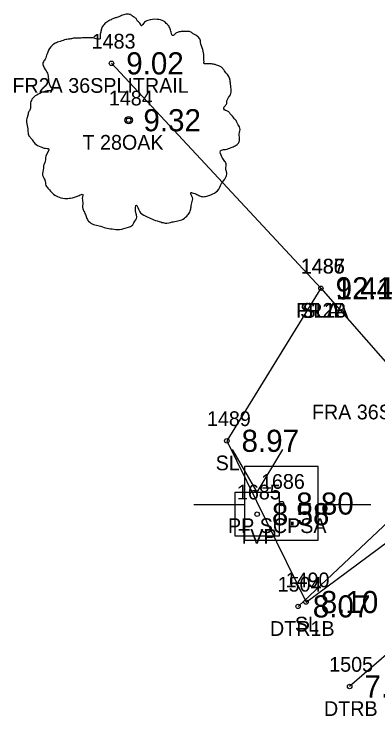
# Model space of a CAD drawing. Extents: x 2608598 to 2610682, y 641451 to 643526.
# Drawn here: x 2608857.57 to 2608882.27, y 643010.54 to 643058.15 of the extents above; entities that cross this region are included whole.
import ezdxf

# ---------------------------------------------------------------- set-up
doc = ezdxf.new("R2010")
doc.units = 0
for name, color, linetype in [('RD_EX_Fence_Other', 7, 'Continuous'), ('RD_EX_Fence_Other_txCode', 7, 'Continuous'), ('RD_EX_H2O', 7, 'Continuous'), ('RD_EX_H2O_txCode', 7, 'Continuous'), ('RD_EX_TX_Fence_Other_ELEV', 7, 'Continuous'), ('RD_EX_TX_H2O_ELEV', 7, 'Continuous'), ('RD_EX_TX_UT_ELEV', 7, 'Continuous'), ('RD_EX_TX_VEG_ELEV', 7, 'Continuous'), ('RD_EX_UT', 7, 'Continuous'), ('RD_EX_UT_txCode', 7, 'Continuous'), ('RD_EX_VEG', 7, 'Continuous'), ('RD_EX_VEG_txCode', 7, 'Continuous'), ('RD_HC_Survey_ELEV', 7, 'Continuous'), ('RD_SMD_Locator', 7, 'Continuous')]:
    doc.layers.add(name, color=color, linetype=linetype)

msp = doc.modelspace()

# ---------------------------------------------------------------- linework, layer by layer
at = {"layer": 'RD_EX_Fence_Other'}
msp.add_line((2608864.186, 643054.805), (2608878.396, 643039.549), dxfattribs=at)
at = {"layer": 'RD_EX_H2O'}
for points in [[(2608899.32, 643029.853), (2608900.685, 643033.3), (2608899.484, 643036.514), (2608896.493, 643036.436), (2608876.847, 643017.975)], [(2608899.32, 643029.853), (2608893.85, 643024.202), (2608880.346, 643012.543)]]:
    msp.add_lwpolyline(points, dxfattribs=at)
at = {"layer": 'RD_EX_UT'}
for p, q in [((2608874.068, 643025.727), (2608872.402, 643028.612)), ((2608874.068, 643025.727), (2608875.809, 643028.612)), ((2608878.212, 643027.457), (2608873.212, 643027.457)), ((2608873.212, 643027.457), (2608873.212, 643022.457)), ((2608878.212, 643022.457), (2608878.212, 643027.457)), ((2608869.781, 643024.895), (2608873.25, 643024.895)), ((2608878.141, 643024.895), (2608881.781, 643024.895)), ((2608873.212, 643022.457), (2608878.212, 643022.457))]:
    msp.add_line(p, q, dxfattribs=at)
msp.add_lwpolyline([(2608872.568, 643022.727), (2608872.568, 643025.727), (2608875.568, 643025.727), (2608875.568, 643022.727)], close=True, dxfattribs=at)
at = {"layer": 'RD_EX_VEG'}
msp.add_line((2608878.396, 643039.549), (2608889.322, 643027.092), dxfattribs=at)
msp.add_lwpolyline([(2608878.396, 643039.549), (2608872.01, 643029.204), (2608877.387, 643018.269), (2608889.322, 643027.092)], dxfattribs=at)
for centre, radius in [((2608865.351, 643050.947), 0.25), ((2608865.339, 643050.928), 0.0001)]:
    msp.add_circle(centre, radius, dxfattribs=at)
for points in [[(2608865.483, 643058.114), (2608865.183, 643058.139), (2608864.859, 643058.039), (2608864.609, 643057.939), (2608864.384, 643057.864), (2608864.159, 643057.764), (2608863.859, 643057.589), (2608863.634, 643057.389), (2608863.509, 643057.139), (2608863.459, 643056.914), (2608863.409, 643056.639), (2608863.409, 643056.464), (2608863.284, 643056.439), (2608863.134, 643056.464), (2608862.884, 643056.539), (2608862.634, 643056.539), (2608862.385, 643056.539), (2608862.035, 643056.514), (2608861.685, 643056.514), (2608861.41, 643056.464), (2608861.085, 643056.415), (2608860.71, 643056.29), (2608860.36, 643056.165), (2608860.061, 643055.915), (2608859.811, 643055.44), (2608859.686, 643055.09), (2608859.536, 643054.84), (2608859.686, 643054.39), (2608859.861, 643054.041), (2608859.886, 643053.841), (2608859.961, 643053.416), (2608860.061, 643053.191), (2608860.186, 643052.991), (2608860.111, 643052.966), (2608859.736, 643052.916), (2608859.436, 643052.816), (2608859.011, 643052.591), (2608858.786, 643052.366), (2608858.686, 643052.041), (2608858.661, 643051.692), (2608858.561, 643051.492), (2608858.486, 643051.217), (2608858.461, 643051.142), (2608858.411, 643050.817), (2608858.511, 643050.367), (2608858.536, 643050.017), (2608858.661, 643049.792), (2608858.811, 643049.618), (2608858.986, 643049.368), (2608859.386, 643049.143), (2608859.711, 643049.043), (2608859.911, 643049.018), (2608859.736, 643048.518), (2608859.686, 643048.168), (2608859.561, 643047.768), (2608859.561, 643047.693), (2608859.511, 643047.219), (2608859.661, 643046.894), (2608859.736, 643046.519), (2608859.911, 643046.294), (2608860.186, 643045.994), (2608860.51, 643045.769), (2608861.01, 643045.644), (2608861.41, 643045.669), (2608861.985, 643045.844), (2608862.235, 643045.919), (2608862.21, 643045.744), (2608862.235, 643045.369), (2608862.235, 643044.945), (2608862.385, 643044.62), (2608862.485, 643044.345), (2608862.634, 643044.095), (2608862.959, 643043.87), (2608863.359, 643043.795), (2608863.784, 643043.645), (2608864.234, 643043.57), (2608864.734, 643043.545), (2608865.333, 643043.695), (2608865.608, 643043.82), (2608865.708, 643043.995), (2608865.908, 643044.37), (2608865.858, 643044.595), (2608865.883, 643045.194), (2608865.983, 643045.019), (2608866.158, 643044.67), (2608866.658, 643044.37), (2608867.058, 643044.195), (2608867.532, 643044.045), (2608867.832, 643043.97), (2608868.307, 643044.045), (2608868.682, 643044.12), (2608869.057, 643044.245), (2608869.357, 643044.52), (2608869.531, 643044.795), (2608869.581, 643045.069), (2608869.656, 643045.444), (2608869.706, 643045.619)], [(2608869.706, 643045.619), (2608869.631, 643045.794), (2608869.581, 643046.044), (2608869.656, 643046.019), (2608869.831, 643045.969), (2608870.106, 643045.844), (2608870.331, 643045.769), (2608870.656, 643045.794), (2608870.931, 643045.894), (2608871.381, 643046.169), (2608871.656, 643046.644), (2608871.93, 643047.044), (2608872.005, 643047.368), (2608871.955, 643047.593), (2608871.93, 643048.093), (2608871.73, 643048.343), (2608871.68, 643048.468), (2608871.581, 643048.868), (2608871.656, 643048.918), (2608871.93, 643048.968), (2608872.305, 643049.093), (2608872.58, 643049.218), (2608872.805, 643049.393), (2608872.88, 643049.618), (2608872.855, 643050.017), (2608872.905, 643050.417), (2608872.83, 643050.567), (2608872.73, 643050.717), (2608872.655, 643050.917), (2608872.505, 643051.067), (2608872.405, 643051.217), (2608872.305, 643051.317), (2608872.18, 643051.467), (2608872.005, 643051.592), (2608871.855, 643051.642), (2608871.805, 643051.792), (2608871.955, 643051.991), (2608872.005, 643052.091), (2608872.03, 643052.316), (2608872.255, 643052.666), (2608872.305, 643053.066), (2608872.255, 643053.491), (2608872.205, 643053.766), (2608872.055, 643054.041), (2608871.855, 643054.29), (2608871.73, 643054.465), (2608871.556, 643054.59), (2608871.231, 643054.715), (2608870.981, 643054.765), (2608870.631, 643054.765), (2608870.431, 643054.815), (2608870.456, 643054.865), (2608870.456, 643055.015), (2608870.456, 643055.29), (2608870.381, 643055.74), (2608870.231, 643056.24), (2608870.231, 643056.265), (2608870.131, 643056.514), (2608869.906, 643056.714), (2608869.731, 643056.814), (2608869.531, 643056.939), (2608869.282, 643056.964), (2608868.982, 643056.964), (2608868.707, 643056.914), (2608868.507, 643056.814), (2608868.332, 643056.689), (2608868.257, 643056.839), (2608868.157, 643057.139), (2608868.107, 643057.289), (2608867.957, 643057.464), (2608867.732, 643057.664), (2608867.282, 643057.789), (2608866.658, 643057.714), (2608866.358, 643057.514), (2608866.208, 643057.339), (2608866.158, 643057.464), (2608865.958, 643057.664), (2608865.858, 643057.839), (2608865.683, 643057.964), (2608865.533, 643058.064), (2608865.433, 643058.114)]]:
    msp.add_spline(points, degree=3, dxfattribs=at)
at = {"layer": 'RD_SMD_Locator'}
for centre in [(2608864.186, 643054.805), (2608865.351, 643050.947), (2608878.396, 643039.549), (2608878.396, 643039.549), (2608878.396, 643039.549), (2608872.01, 643029.204), (2608875.721, 643024.948), (2608874.068, 643024.227), (2608877.387, 643018.269), (2608876.847, 643017.975), (2608880.346, 643012.543)]:
    msp.add_circle(centre, 0.15, dxfattribs=at)

# ---------------------------------------------------------------- texts
at = {"layer": 'RD_EX_Fence_Other_txCode'}
for s, p in [('1483', (2608862.839, 643055.805)), ('FR2A 36SPLITRAIL', (2608857.461, 643052.805)), ('1485', (2608877.05, 643040.549)), ('FR2B', (2608876.719, 643037.549)), ('FRA 36SPLITRAIL', (2608877.786, 643030.659))]:
    msp.add_text(s, height=1, dxfattribs=at).set_placement(p)
at = {"layer": 'RD_EX_H2O_txCode'}
for s, p in [('1504', (2608875.461, 643018.975)), ('DTR1B', (2608874.941, 643015.975)), ('1505', (2608878.96, 643013.543)), ('DTRB', (2608878.606, 643010.543))]:
    msp.add_text(s, height=1, dxfattribs=at).set_placement(p)
at = {"layer": 'RD_EX_TX_Fence_Other_ELEV'}
for s, p in [('9.02', (2608865.186, 643054.055)), ('9.41', (2608879.396, 643038.799))]:
    msp.add_text(s, height=1.5, dxfattribs=at).set_placement(p)
at = {"layer": 'RD_EX_TX_H2O_ELEV'}
for s, p in [('8.07', (2608877.847, 643017.225)), ('7.90', (2608881.346, 643011.793))]:
    msp.add_text(s, height=1.5, dxfattribs=at).set_placement(p)
at = {"layer": 'RD_EX_TX_UT_ELEV'}
msp.add_text('8.58', height=1.5, dxfattribs=at).set_placement((2608875.068, 643023.477))
at = {"layer": 'RD_EX_TX_VEG_ELEV'}
for s, p in [('9.32', (2608866.351, 643050.197)), ('9.41', (2608879.396, 643038.799)), ('12.41', (2608879.396, 643038.799)), ('8.97', (2608873.01, 643028.454)), ('8.10', (2608878.387, 643017.519))]:
    msp.add_text(s, height=1.5, dxfattribs=at).set_placement(p)
at = {"layer": 'RD_EX_UT_txCode'}
for s, p in [('1686', (2608874.328, 643025.948)), ('1685', (2608872.698, 643025.227)), ('PP SCPSA', (2608872.091, 643022.948)), ('TVP', (2608872.785, 643022.227))]:
    msp.add_text(s, height=1, dxfattribs=at).set_placement(p)
at = {"layer": 'RD_EX_VEG_txCode'}
for s, p in [('1484', (2608864.005, 643051.947)), ('T 28OAK', (2608862.217, 643048.947)), ('1486', (2608877.026, 643040.549)), ('1487', (2608877.05, 643040.549)), ('SL1A', (2608876.987, 643037.549)), ('SLA', (2608877.152, 643037.549)), ('1489', (2608870.664, 643030.204)), ('SL', (2608871.254, 643027.204)), ('1490', (2608876.001, 643019.269)), ('SL', (2608876.631, 643016.269))]:
    msp.add_text(s, height=1, dxfattribs=at).set_placement(p)
at = {"layer": 'RD_HC_Survey_ELEV'}
msp.add_text('8.80', height=1.5, dxfattribs=at).set_placement((2608876.721, 643024.198))

doc.saveas('drawing.dxf')
